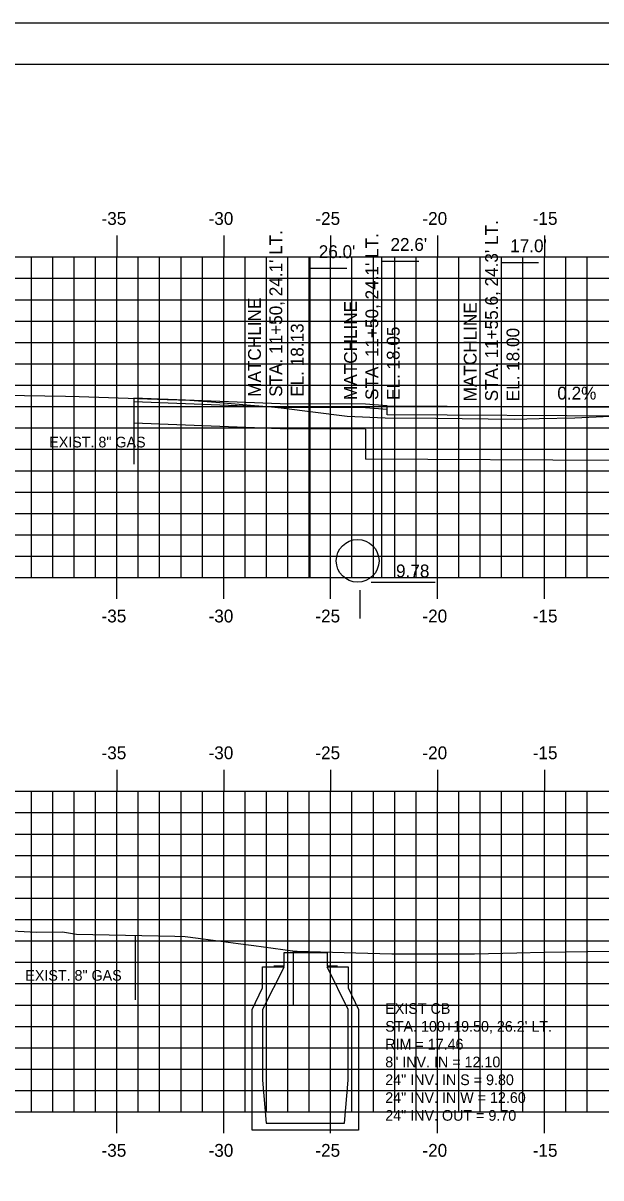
# Model space of a CAD drawing. Extents: x 1023237 to 1023407, y 394697 to 394807.
# Drawn here: x 1023280.3 to 1023307.3, y 394752.5 to 394806.5 of the extents above; entities that cross this region are included whole.
import ezdxf

# ---------------------------------------------------------------- set-up
doc = ezdxf.new("R2010")
doc.units = 0
for name, color, linetype in [('ANNOTATION', 7, 'Continuous'), ('BORDER', 7, 'Continuous'), ('D_Drainage_Culvert', 7, 'Continuous'), ('D_Drainage_Text', 7, 'Continuous'), ('D_Roadway_Edge_TW', 7, 'Continuous'), ('D_Roadway_Pavement', 7, 'Continuous'), ('D_Roadway_SubGrade', 7, 'Continuous'), ('D_Text_Monospaced', 7, 'Continuous'), ('DIMENSIONS', 7, 'Continuous'), ('H_V ANNOTATION', 7, 'Continuous'), ('MAJOR', 7, 'Continuous'), ('MINOR', 7, 'Continuous'), ('PLOT BOUNDARY', 7, 'Continuous'), ('S_Drainage_CB', 7, 'Continuous'), ('S_Roadway_Centerline', 7, 'Continuous'), ('S_Roadway_Edge_Pavement', 7, 'Continuous'), ('S_Utilities_UG_Gas_Line', 7, 'Continuous')]:
    doc.layers.add(name, color=color, linetype=linetype)

msp = doc.modelspace()

# ---------------------------------------------------------------- linework, layer by layer
at = {"layer": 'ANNOTATION'}
for p, q in [((1023297.063, 394780.607), (1023297.063, 394795.607)), ((1023298.786, 394795.398), (1023297.063, 394795.398)), ((1023304.386, 394795.335), (1023302.663, 394795.335)), ((1023295.429, 394795.059), (1023293.706, 394795.059)), ((1023296.05, 394778.686), (1023296.05, 394780.016))]:
    msp.add_line(p, q, dxfattribs=at)
at = {"layer": 'BORDER'}
msp.add_line((1023404.664, 394804.607), (1023244.664, 394804.607), dxfattribs=at)
at = {"layer": 'D_Drainage_Culvert'}
msp.add_circle((1023295.927, 394781.387), 1, dxfattribs=at)
at = {"layer": 'D_Drainage_Text'}
msp.add_line((1023296.553, 394780.387), (1023299.552, 394780.387), dxfattribs=at)
at = {"layer": 'D_Roadway_Edge_TW'}
for p, q in [((1023297.301, 394788.383), (1023297.301, 394788.633)), ((1023297.301, 394788.633), (1023319.663, 394788.518))]:
    msp.add_line(p, q, dxfattribs=at)
at = {"layer": 'D_Roadway_Pavement'}
for p, q in [((1023297.301, 394788.216), (1023297.301, 394788.383)), ((1023319.663, 394788.101), (1023297.301, 394788.216))]:
    msp.add_line(p, q, dxfattribs=at)
at = {"layer": 'D_Roadway_SubGrade'}
msp.add_lwpolyline([(1023343.226, 394785.785), (1023319.663, 394786.018), (1023296.301, 394786.138)], dxfattribs=at)
at = {"layer": 'DIMENSIONS'}
for p, q in [((1023293.706, 394780.607), (1023293.706, 394795.607)), ((1023302.663, 394780.607), (1023302.663, 394795.607)), ((1023292.301, 394788.733), (1023285.452, 394788.993)), ((1023285.452, 394788.993), (1023285.452, 394787.826)), ((1023292.301, 394788.566), (1023285.452, 394788.826)), ((1023296.301, 394788.713), (1023292.301, 394788.733)), ((1023296.301, 394788.546), (1023292.301, 394788.566)), ((1023297.301, 394788.633), (1023296.301, 394788.713)), ((1023297.301, 394788.466), (1023296.301, 394788.546)), ((1023292.301, 394787.566), (1023285.452, 394787.826)), ((1023296.301, 394787.546), (1023292.301, 394787.566)), ((1023296.301, 394787.546), (1023296.301, 394786.138))]:
    msp.add_line(p, q, dxfattribs=at)
at = {"layer": 'MAJOR'}
for p, q in [((1023284.663, 394796.609), (1023284.663, 394795.607)), ((1023289.663, 394796.609), (1023289.663, 394795.607)), ((1023294.663, 394796.609), (1023294.663, 394795.607)), ((1023299.663, 394796.609), (1023299.663, 394795.607)), ((1023304.663, 394796.609), (1023304.663, 394795.607)), ((1023249.663, 394795.607), (1023389.663, 394795.607)), ((1023284.663, 394780.607), (1023284.663, 394795.607)), ((1023289.663, 394780.607), (1023289.663, 394795.607)), ((1023294.663, 394780.607), (1023294.663, 394795.607)), ((1023299.663, 394780.607), (1023299.663, 394795.607)), ((1023304.663, 394780.607), (1023304.663, 394795.607)), ((1023249.663, 394790.607), (1023389.663, 394790.607)), ((1023249.663, 394785.607), (1023389.663, 394785.607)), ((1023249.663, 394780.607), (1023389.663, 394780.607)), ((1023284.663, 394779.605), (1023284.663, 394780.607)), ((1023289.663, 394779.605), (1023289.663, 394780.607)), ((1023294.663, 394779.605), (1023294.663, 394780.607)), ((1023299.663, 394779.605), (1023299.663, 394780.607)), ((1023304.663, 394779.605), (1023304.663, 394780.607)), ((1023284.663, 394771.609), (1023284.663, 394770.607)), ((1023289.663, 394771.609), (1023289.663, 394770.607)), ((1023294.663, 394771.609), (1023294.663, 394770.607)), ((1023299.663, 394771.609), (1023299.663, 394770.607)), ((1023304.663, 394771.609), (1023304.663, 394770.607)), ((1023249.663, 394770.607), (1023389.663, 394770.607)), ((1023284.663, 394755.607), (1023284.663, 394770.607)), ((1023289.663, 394755.607), (1023289.663, 394770.607)), ((1023294.663, 394755.607), (1023294.663, 394770.607)), ((1023299.663, 394755.607), (1023299.663, 394770.607)), ((1023304.663, 394755.607), (1023304.663, 394770.607)), ((1023249.663, 394765.607), (1023389.663, 394765.607)), ((1023249.663, 394760.607), (1023389.663, 394760.607)), ((1023249.663, 394755.607), (1023389.663, 394755.607)), ((1023284.663, 394754.605), (1023284.663, 394755.607)), ((1023289.663, 394754.605), (1023289.663, 394755.607)), ((1023294.663, 394754.605), (1023294.663, 394755.607)), ((1023299.663, 394754.605), (1023299.663, 394755.607)), ((1023304.663, 394754.605), (1023304.663, 394755.607))]:
    msp.add_line(p, q, dxfattribs=at)
at = {"layer": 'MINOR'}
for p, q in [((1023280.663, 394780.607), (1023280.663, 394795.607)), ((1023281.663, 394780.607), (1023281.663, 394795.607)), ((1023282.663, 394780.607), (1023282.663, 394795.607)), ((1023283.663, 394780.607), (1023283.663, 394795.607)), ((1023285.663, 394780.607), (1023285.663, 394795.607)), ((1023286.663, 394780.607), (1023286.663, 394795.607)), ((1023287.663, 394780.607), (1023287.663, 394795.607)), ((1023288.663, 394780.607), (1023288.663, 394795.607)), ((1023290.663, 394780.607), (1023290.663, 394795.607)), ((1023291.663, 394780.607), (1023291.663, 394795.607)), ((1023292.663, 394780.607), (1023292.663, 394795.607)), ((1023293.663, 394780.607), (1023293.663, 394795.607)), ((1023295.663, 394780.607), (1023295.663, 394795.607)), ((1023296.663, 394780.607), (1023296.663, 394795.607)), ((1023297.663, 394780.607), (1023297.663, 394795.607)), ((1023298.663, 394780.607), (1023298.663, 394795.607)), ((1023300.663, 394780.607), (1023300.663, 394795.607)), ((1023301.663, 394780.607), (1023301.663, 394795.607)), ((1023302.663, 394780.607), (1023302.663, 394795.607)), ((1023303.663, 394780.607), (1023303.663, 394795.607)), ((1023305.663, 394780.607), (1023305.663, 394795.607)), ((1023306.663, 394780.607), (1023306.663, 394795.607)), ((1023249.663, 394794.607), (1023389.663, 394794.607)), ((1023249.663, 394793.607), (1023389.663, 394793.607)), ((1023249.663, 394792.607), (1023389.663, 394792.607)), ((1023249.663, 394791.607), (1023389.663, 394791.607)), ((1023249.663, 394789.607), (1023389.663, 394789.607)), ((1023249.663, 394788.607), (1023389.663, 394788.607)), ((1023249.663, 394787.607), (1023389.663, 394787.607)), ((1023249.663, 394786.607), (1023389.663, 394786.607)), ((1023249.663, 394784.607), (1023389.663, 394784.607)), ((1023249.663, 394783.607), (1023389.663, 394783.607)), ((1023249.663, 394782.607), (1023389.663, 394782.607)), ((1023249.663, 394781.607), (1023389.663, 394781.607)), ((1023280.663, 394755.607), (1023280.663, 394770.607)), ((1023281.663, 394755.607), (1023281.663, 394770.607)), ((1023282.663, 394755.607), (1023282.663, 394770.607)), ((1023283.663, 394755.607), (1023283.663, 394770.607)), ((1023285.663, 394755.607), (1023285.663, 394770.607)), ((1023286.663, 394755.607), (1023286.663, 394770.607)), ((1023287.663, 394755.607), (1023287.663, 394770.607)), ((1023288.663, 394755.607), (1023288.663, 394770.607)), ((1023290.663, 394755.607), (1023290.663, 394770.607)), ((1023291.663, 394755.607), (1023291.663, 394770.607)), ((1023292.663, 394755.607), (1023292.663, 394770.607)), ((1023293.663, 394755.607), (1023293.663, 394770.607)), ((1023295.663, 394755.607), (1023295.663, 394770.607)), ((1023296.663, 394755.607), (1023296.663, 394770.607)), ((1023297.663, 394755.607), (1023297.663, 394770.607)), ((1023298.663, 394755.607), (1023298.663, 394770.607)), ((1023300.663, 394755.607), (1023300.663, 394770.607)), ((1023301.663, 394755.607), (1023301.663, 394770.607)), ((1023302.663, 394755.607), (1023302.663, 394770.607)), ((1023303.663, 394755.607), (1023303.663, 394770.607)), ((1023305.663, 394755.607), (1023305.663, 394770.607)), ((1023306.663, 394755.607), (1023306.663, 394770.607)), ((1023249.663, 394769.607), (1023389.663, 394769.607)), ((1023249.663, 394768.607), (1023389.663, 394768.607)), ((1023249.663, 394767.607), (1023389.663, 394767.607)), ((1023249.663, 394766.607), (1023389.663, 394766.607)), ((1023249.663, 394764.607), (1023389.663, 394764.607)), ((1023249.663, 394763.607), (1023389.663, 394763.607)), ((1023249.663, 394762.607), (1023389.663, 394762.607)), ((1023249.663, 394761.607), (1023389.663, 394761.607)), ((1023249.663, 394759.607), (1023389.663, 394759.607)), ((1023249.663, 394758.607), (1023389.663, 394758.607)), ((1023249.663, 394757.607), (1023389.663, 394757.607)), ((1023249.663, 394756.607), (1023389.663, 394756.607))]:
    msp.add_line(p, q, dxfattribs=at)
at = {"layer": 'PLOT BOUNDARY'}
msp.add_lwpolyline([(1023236.57, 394696.548), (1023406.57, 394696.548), (1023406.57, 394806.548), (1023236.57, 394806.548)], close=True, dxfattribs=at)
at = {"layer": 'S_Drainage_CB'}
for p, q in [((1023291.48, 394761.413), (1023291.48, 394762.398)), ((1023291.48, 394762.398), (1023292.497, 394762.398)), ((1023292.497, 394762.398), (1023291.48, 394760.396)), ((1023294.498, 394762.398), (1023295.482, 394762.398)), ((1023295.482, 394760.396), (1023294.498, 394762.398)), ((1023295.482, 394762.398), (1023295.482, 394761.413)), ((1023290.988, 394760.396), (1023291.48, 394761.413)), ((1023295.482, 394761.413), (1023295.974, 394760.396)), ((1023290.988, 394754.753), (1023290.988, 394760.396)), ((1023291.48, 394760.396), (1023291.48, 394757.083)), ((1023295.482, 394757.083), (1023295.482, 394760.396)), ((1023295.974, 394760.396), (1023295.974, 394754.753)), ((1023291.48, 394757.083), (1023291.644, 394755.081)), ((1023295.318, 394755.081), (1023295.482, 394757.083)), ((1023291.644, 394755.081), (1023295.318, 394755.081)), ((1023295.974, 394754.753), (1023290.988, 394754.753))]:
    msp.add_line(p, q, dxfattribs=at)
msp.add_lwpolyline([(1023292.005, 394762.439), (1023292.497, 394762.439), (1023292.497, 394763.063), (1023294.498, 394763.063), (1023294.498, 394762.439), (1023294.99, 394762.439)], dxfattribs=at)
at = {"layer": 'S_Roadway_Centerline'}
for points in [[(1023279.371, 394789.138), (1023282.267, 394789.087), (1023282.895, 394789.083), (1023287.012, 394788.937), (1023288.069, 394788.902), (1023289.289, 394788.806), (1023291.107, 394788.662), (1023291.901, 394788.6), (1023292.353, 394788.545), (1023295.438, 394788.156), (1023297.21, 394788.076), (1023299.582, 394788.057), (1023303.266, 394788.022), (1023304.419, 394788.05), (1023306.096, 394788.075), (1023311.046, 394788.308)], [(1023279.171, 394764.101), (1023280.89, 394764.015), (1023282.125, 394764.03), (1023282.78, 394763.921), (1023285.823, 394763.855), (1023287.367, 394763.821), (1023287.859, 394763.806), (1023287.987, 394763.796), (1023288.693, 394763.711), (1023290.344, 394763.486), (1023291.072, 394763.388), (1023292.875, 394763.144), (1023292.904, 394763.13), (1023293.092, 394763.128), (1023295.838, 394763.047), (1023297.53, 394763.007), (1023301.388, 394763.001), (1023303.369, 394763.045), (1023304.631, 394763.082), (1023306.691, 394763.108), (1023309.89, 394763.162)]]:
    msp.add_lwpolyline(points, dxfattribs=at)
at = {"layer": 'S_Roadway_Edge_Pavement'}
msp.add_line((1023292.904, 394763.13), (1023292.904, 394760.63), dxfattribs=at)
at = {"layer": 'S_Utilities_UG_Gas_Line'}
for p, q in [((1023285.452, 394788.904), (1023285.452, 394785.904)), ((1023285.52, 394763.845), (1023285.52, 394760.845))]:
    msp.add_line(p, q, dxfattribs=at)

# ---------------------------------------------------------------- texts
at = {"layer": 'ANNOTATION'}
for s, rotation, p in [("STA. 11+55.6, 24.3' LT.", 90, (1023302.493, 394788.851)), ("STA. 11+50, 24.1' LT.", 90, (1023292.4, 394789.063)), ("STA. 11+50, 24.1' LT.", 90, (1023296.893, 394788.914)), ('MATCHLINE', 90, (1023291.4, 394789.063)), ('MATCHLINE', 90, (1023295.893, 394788.914)), ('MATCHLINE', 90, (1023301.493, 394788.851)), ('EL. 18.13', 90, (1023293.4, 394789.063)), ('EL. 18.05', 90, (1023297.893, 394788.914)), ('EL. 18.00', 90, (1023303.493, 394788.851)), ('0.2%', 359.8983, (1023305.268, 394788.936))]:
    msp.add_text(s, height=0.6, rotation=rotation, dxfattribs=at).set_placement(p)
for s, p in [("22.6'", (1023297.464, 394795.892)), ("17.0'", (1023303.064, 394795.829)), ("26.0'", (1023294.107, 394795.553))]:
    msp.add_text(s, height=0.6, dxfattribs=at).set_placement(p)
at = {"layer": 'D_Drainage_Text'}
msp.add_text('9.78', height=0.6, dxfattribs=at).set_placement((1023297.724, 394780.616))
at = {"layer": 'D_Text_Monospaced'}
for s, height, p in [('EXIST. 8" GAS', 0.49998, (1023281.497, 394786.695)), ('EXIST. 8" GAS', 0.49998, (1023280.379, 394761.745)), ('EXIST CB', 0.5, (1023297.219, 394760.192)), ("STA. 100+19.50, 26.2' LT.", 0.49998, (1023297.219, 394759.359)), ('RIM = 17.46', 0.49998, (1023297.219, 394758.525)), ('8" INV. IN = 12.10', 0.49998, (1023297.219, 394757.692)), ('24" INV. IN S = 9.80', 0.49998, (1023297.219, 394756.859)), ('24" INV. IN W = 12.60', 0.49998, (1023297.219, 394756.025)), ('24" INV. OUT = 9.70', 0.49998, (1023297.219, 394755.192))]:
    msp.add_text(s, height=height, dxfattribs=at).set_placement(p)
at = {"layer": 'H_V ANNOTATION'}
for s, p in [('-35', (1023283.944, 394797.107)), ('-30', (1023288.952, 394797.107)), ('-25', (1023293.949, 394797.107)), ('-20', (1023298.957, 394797.107)), ('-15', (1023304.12, 394797.107)), ('-35', (1023283.944, 394778.507)), ('-30', (1023288.952, 394778.507)), ('-25', (1023293.949, 394778.507)), ('-20', (1023298.957, 394778.507)), ('-15', (1023304.12, 394778.507)), ('-35', (1023283.944, 394772.107)), ('-30', (1023288.952, 394772.107)), ('-25', (1023293.949, 394772.107)), ('-20', (1023298.957, 394772.107)), ('-15', (1023304.12, 394772.107)), ('-35', (1023283.944, 394753.507)), ('-30', (1023288.952, 394753.507)), ('-25', (1023293.949, 394753.507)), ('-20', (1023298.957, 394753.507)), ('-15', (1023304.12, 394753.507))]:
    msp.add_text(s, height=0.6, dxfattribs=at).set_placement(p)

doc.saveas('drawing.dxf')
